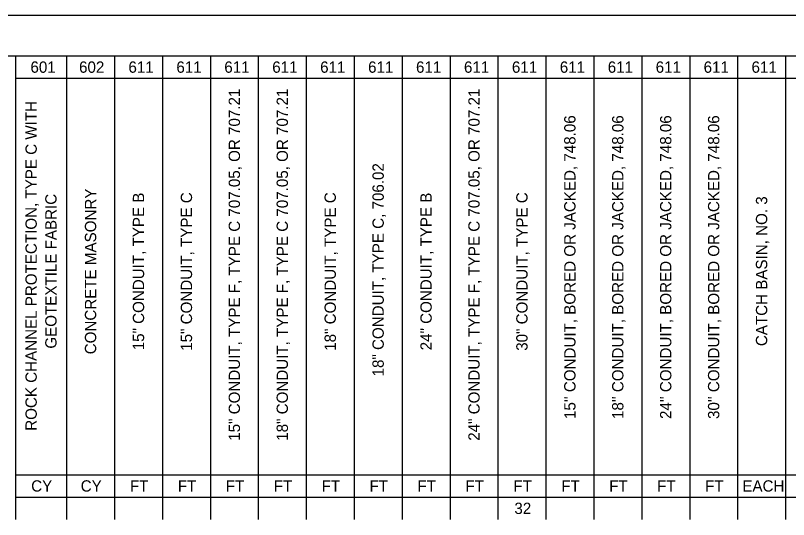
# Model space of a CAD drawing. Extents: x 0.2 to 34.2, y 0 to 22.
# Drawn here: x 14.91 to 24.47, y 15.79 to 22.03 of the extents above; entities that cross this region are included whole.
import ezdxf

# ---------------------------------------------------------------- set-up
doc = ezdxf.new("R2010")
doc.units = 0
for name, color, linetype in [('SH_Border', 7, 'Continuous'), ('SH_Cut_Line', 7, 'Continuous'), ('SH_Text', 7, 'Continuous')]:
    doc.layers.add(name, color=color, linetype=linetype)

msp = doc.modelspace()

# ---------------------------------------------------------------- linework, layer by layer
at = {"layer": 'SH_Border'}
msp.add_lwpolyline([(1.692, 21.5253), (33.692, 21.5253), (33.692, 0.5253), (1.692, 0.5253)], close=True, dxfattribs=at)
at = {"layer": 'SH_Cut_Line'}
msp.add_lwpolyline([(0.192, 0.0253), (34.192, 0.0253), (34.192, 22.0253), (0.192, 22.0253)], close=True, dxfattribs=at)
at = {"layer": 'SH_Text'}
for p, q in [((14.908, 21.5253), (15.5405, 21.5253)), ((14.908, 21.5253), (14.908, 21.2486)), ((15.5405, 21.5253), (24.4346, 21.5253)), ((15.5405, 21.5253), (15.5405, 21.2486)), ((16.1334, 21.5253), (16.1334, 21.2486)), ((16.7264, 21.5253), (16.7264, 21.2486)), ((17.3193, 21.5253), (17.3193, 21.2486)), ((17.9122, 21.5253), (17.9122, 21.2486)), ((18.5052, 21.5253), (18.5052, 21.2486)), ((19.0981, 21.5253), (19.0981, 21.2486)), ((19.6911, 21.5253), (19.6911, 21.2486)), ((20.284, 21.5253), (20.284, 21.2486)), ((20.8769, 21.5253), (20.8769, 21.2486)), ((21.4699, 21.5253), (21.4699, 21.2486)), ((22.0628, 21.5253), (22.0628, 21.2486)), ((22.6558, 21.5253), (22.6558, 21.2486)), ((23.2487, 21.5253), (23.2487, 21.2486)), ((23.8417, 21.5253), (23.8417, 21.2486)), ((24.4346, 21.5253), (32.1955, 21.5253)), ((24.4346, 21.5253), (24.4346, 21.2486)), ((14.908, 21.2486), (15.5405, 21.2486)), ((14.908, 21.2486), (14.908, 20.9719)), ((15.5405, 21.2486), (24.4346, 21.2486)), ((15.5405, 21.2486), (15.5405, 20.9719)), ((16.1334, 21.2486), (16.1334, 20.9719)), ((16.7264, 21.2486), (16.7264, 20.9719)), ((17.3193, 21.2486), (17.3193, 20.9719)), ((17.9122, 21.2486), (17.9122, 20.9719)), ((18.5052, 21.2486), (18.5052, 20.9719)), ((19.0981, 21.2486), (19.0981, 20.9719)), ((19.6911, 21.2486), (19.6911, 20.9719)), ((20.284, 21.2486), (20.284, 20.9719)), ((20.8769, 21.2486), (20.8769, 20.9719)), ((21.4699, 21.2486), (21.4699, 20.9719)), ((22.0628, 21.2486), (22.0628, 20.9719)), ((22.6558, 21.2486), (22.6558, 20.9719)), ((23.2487, 21.2486), (23.2487, 20.9719)), ((23.8417, 21.2486), (23.8417, 20.9719)), ((24.4346, 21.2486), (32.1955, 21.2486)), ((24.4346, 21.2486), (24.4346, 20.9719)), ((14.908, 20.9719), (14.908, 20.6952)), ((15.5405, 20.9719), (15.5405, 20.6952)), ((16.1334, 20.9719), (16.1334, 20.6952)), ((16.7264, 20.9719), (16.7264, 20.6952)), ((17.3193, 20.9719), (17.3193, 20.6952)), ((17.9122, 20.9719), (17.9122, 20.6952)), ((18.5052, 20.9719), (18.5052, 20.6952)), ((19.0981, 20.9719), (19.0981, 20.6952)), ((19.6911, 20.9719), (19.6911, 20.6952)), ((20.284, 20.9719), (20.284, 20.6952)), ((20.8769, 20.9719), (20.8769, 20.6952)), ((21.4699, 20.9719), (21.4699, 20.6952)), ((22.0628, 20.9719), (22.0628, 20.6952)), ((22.6558, 20.9719), (22.6558, 20.6952)), ((23.2487, 20.9719), (23.2487, 20.6952)), ((23.8417, 20.9719), (23.8417, 20.6952)), ((24.4346, 20.9719), (24.4346, 20.6952)), ((14.908, 20.6952), (14.908, 20.4184)), ((15.5405, 20.6952), (15.5405, 20.4184)), ((16.1334, 20.6952), (16.1334, 20.4184)), ((16.7264, 20.6952), (16.7264, 20.4184)), ((17.3193, 20.6952), (17.3193, 20.4184)), ((17.9122, 20.6952), (17.9122, 20.4184)), ((18.5052, 20.6952), (18.5052, 20.4184)), ((19.0981, 20.6952), (19.0981, 20.4184)), ((19.6911, 20.6952), (19.6911, 20.4184)), ((20.284, 20.6952), (20.284, 20.4184)), ((20.8769, 20.6952), (20.8769, 20.4184)), ((21.4699, 20.6952), (21.4699, 20.4184)), ((22.0628, 20.6952), (22.0628, 20.4184)), ((22.6558, 20.6952), (22.6558, 20.4184)), ((23.2487, 20.6952), (23.2487, 20.4184)), ((23.8417, 20.6952), (23.8417, 20.4184)), ((24.4346, 20.6952), (24.4346, 20.4184)), ((14.908, 20.4184), (14.908, 20.1417)), ((15.5405, 20.4184), (15.5405, 20.1417)), ((16.1334, 20.4184), (16.1334, 20.1417)), ((16.7264, 20.4184), (16.7264, 20.1417)), ((17.3193, 20.4184), (17.3193, 20.1417)), ((17.9122, 20.4184), (17.9122, 20.1417)), ((18.5052, 20.4184), (18.5052, 20.1417)), ((19.0981, 20.4184), (19.0981, 20.1417)), ((19.6911, 20.4184), (19.6911, 20.1417)), ((20.284, 20.4184), (20.284, 20.1417)), ((20.8769, 20.4184), (20.8769, 20.1417)), ((21.4699, 20.4184), (21.4699, 20.1417)), ((22.0628, 20.4184), (22.0628, 20.1417)), ((22.6558, 20.4184), (22.6558, 20.1417)), ((23.2487, 20.4184), (23.2487, 20.1417)), ((23.8417, 20.4184), (23.8417, 20.1417)), ((24.4346, 20.4184), (24.4346, 20.1417)), ((14.908, 20.1417), (14.908, 19.865)), ((15.5405, 20.1417), (15.5405, 19.865)), ((16.1334, 20.1417), (16.1334, 19.865)), ((16.7264, 20.1417), (16.7264, 19.865)), ((17.3193, 20.1417), (17.3193, 19.865)), ((17.9122, 20.1417), (17.9122, 19.865)), ((18.5052, 20.1417), (18.5052, 19.865)), ((19.0981, 20.1417), (19.0981, 19.865)), ((19.6911, 20.1417), (19.6911, 19.865)), ((20.284, 20.1417), (20.284, 19.865)), ((20.8769, 20.1417), (20.8769, 19.865)), ((21.4699, 20.1417), (21.4699, 19.865)), ((22.0628, 20.1417), (22.0628, 19.865)), ((22.6558, 20.1417), (22.6558, 19.865)), ((23.2487, 20.1417), (23.2487, 19.865)), ((23.8417, 20.1417), (23.8417, 19.865)), ((24.4346, 20.1417), (24.4346, 19.865)), ((14.908, 19.865), (14.908, 19.5883)), ((15.5405, 19.865), (15.5405, 19.5883)), ((16.1334, 19.865), (16.1334, 19.5883)), ((16.7264, 19.865), (16.7264, 19.5883)), ((17.3193, 19.865), (17.3193, 19.5883)), ((17.9122, 19.865), (17.9122, 19.5883)), ((18.5052, 19.865), (18.5052, 19.5883)), ((19.0981, 19.865), (19.0981, 19.5883)), ((19.6911, 19.865), (19.6911, 19.5883)), ((20.284, 19.865), (20.284, 19.5883)), ((20.8769, 19.865), (20.8769, 19.5883)), ((21.4699, 19.865), (21.4699, 19.5883)), ((22.0628, 19.865), (22.0628, 19.5883)), ((22.6558, 19.865), (22.6558, 19.5883)), ((23.2487, 19.865), (23.2487, 19.5883)), ((23.8417, 19.865), (23.8417, 19.5883)), ((24.4346, 19.865), (24.4346, 19.5883)), ((14.908, 19.5883), (14.908, 19.3116)), ((15.5405, 19.5883), (15.5405, 19.3116)), ((16.1334, 19.5883), (16.1334, 19.3116)), ((16.7264, 19.5883), (16.7264, 19.3116)), ((17.3193, 19.5883), (17.3193, 19.3116)), ((17.9122, 19.5883), (17.9122, 19.3116)), ((18.5052, 19.5883), (18.5052, 19.3116)), ((19.0981, 19.5883), (19.0981, 19.3116)), ((19.6911, 19.5883), (19.6911, 19.3116)), ((20.284, 19.5883), (20.284, 19.3116)), ((20.8769, 19.5883), (20.8769, 19.3116)), ((21.4699, 19.5883), (21.4699, 19.3116)), ((22.0628, 19.5883), (22.0628, 19.3116)), ((22.6558, 19.5883), (22.6558, 19.3116)), ((23.2487, 19.5883), (23.2487, 19.3116)), ((23.8417, 19.5883), (23.8417, 19.3116)), ((24.4346, 19.5883), (24.4346, 19.3116)), ((14.908, 19.3116), (14.908, 19.0349)), ((15.5405, 19.3116), (15.5405, 19.0349)), ((16.1334, 19.3116), (16.1334, 19.0349)), ((16.7264, 19.3116), (16.7264, 19.0349)), ((17.3193, 19.3116), (17.3193, 19.0349)), ((17.9122, 19.3116), (17.9122, 19.0349)), ((18.5052, 19.3116), (18.5052, 19.0349)), ((19.0981, 19.3116), (19.0981, 19.0349)), ((19.6911, 19.3116), (19.6911, 19.0349)), ((20.284, 19.3116), (20.284, 19.0349)), ((20.8769, 19.3116), (20.8769, 19.0349)), ((21.4699, 19.3116), (21.4699, 19.0349)), ((22.0628, 19.3116), (22.0628, 19.0349)), ((22.6558, 19.3116), (22.6558, 19.0349)), ((23.2487, 19.3116), (23.2487, 19.0349)), ((23.8417, 19.3116), (23.8417, 19.0349)), ((24.4346, 19.3116), (24.4346, 19.0349)), ((14.908, 19.0349), (14.908, 18.7582)), ((15.5405, 19.0349), (15.5405, 18.7582)), ((16.1334, 19.0349), (16.1334, 18.7582)), ((16.7264, 19.0349), (16.7264, 18.7582)), ((17.3193, 19.0349), (17.3193, 18.7582)), ((17.9122, 19.0349), (17.9122, 18.7582)), ((18.5052, 19.0349), (18.5052, 18.7582)), ((19.0981, 19.0349), (19.0981, 18.7582)), ((19.6911, 19.0349), (19.6911, 18.7582)), ((20.284, 19.0349), (20.284, 18.7582)), ((20.8769, 19.0349), (20.8769, 18.7582)), ((21.4699, 19.0349), (21.4699, 18.7582)), ((22.0628, 19.0349), (22.0628, 18.7582)), ((22.6558, 19.0349), (22.6558, 18.7582)), ((23.2487, 19.0349), (23.2487, 18.7582)), ((23.8417, 19.0349), (23.8417, 18.7582)), ((24.4346, 19.0349), (24.4346, 18.7582)), ((14.908, 18.7582), (14.908, 18.4815)), ((15.5405, 18.7582), (15.5405, 18.4815)), ((16.1334, 18.7582), (16.1334, 18.4815)), ((16.7264, 18.7582), (16.7264, 18.4815)), ((17.3193, 18.7582), (17.3193, 18.4815)), ((17.9122, 18.7582), (17.9122, 18.4815)), ((18.5052, 18.7582), (18.5052, 18.4815)), ((19.0981, 18.7582), (19.0981, 18.4815)), ((19.6911, 18.7582), (19.6911, 18.4815)), ((20.284, 18.7582), (20.284, 18.4815)), ((20.8769, 18.7582), (20.8769, 18.4815)), ((21.4699, 18.7582), (21.4699, 18.4815)), ((22.0628, 18.7582), (22.0628, 18.4815)), ((22.6558, 18.7582), (22.6558, 18.4815)), ((23.2487, 18.7582), (23.2487, 18.4815)), ((23.8417, 18.7582), (23.8417, 18.4815)), ((24.4346, 18.7582), (24.4346, 18.4815)), ((14.908, 18.4815), (14.908, 18.2048)), ((15.5405, 18.4815), (15.5405, 18.2048)), ((16.1334, 18.4815), (16.1334, 18.2048)), ((16.7264, 18.4815), (16.7264, 18.2048)), ((17.3193, 18.4815), (17.3193, 18.2048)), ((17.9122, 18.4815), (17.9122, 18.2048)), ((18.5052, 18.4815), (18.5052, 18.2048)), ((19.0981, 18.4815), (19.0981, 18.2048)), ((19.6911, 18.4815), (19.6911, 18.2048)), ((20.284, 18.4815), (20.284, 18.2048)), ((20.8769, 18.4815), (20.8769, 18.2048)), ((21.4699, 18.4815), (21.4699, 18.2048)), ((22.0628, 18.4815), (22.0628, 18.2048)), ((22.6558, 18.4815), (22.6558, 18.2048)), ((23.2487, 18.4815), (23.2487, 18.2048)), ((23.8417, 18.4815), (23.8417, 18.2048)), ((24.4346, 18.4815), (24.4346, 18.2048)), ((14.908, 18.2048), (14.908, 16.3469)), ((15.5405, 18.2048), (15.5405, 16.3469)), ((16.1334, 18.2048), (16.1334, 16.3469)), ((16.7264, 18.2048), (16.7264, 16.3469)), ((17.3193, 18.2048), (17.3193, 16.3469)), ((17.9122, 18.2048), (17.9122, 16.3469)), ((18.5052, 18.2048), (18.5052, 16.3469)), ((19.0981, 18.2048), (19.0981, 16.3469)), ((19.6911, 18.2048), (19.6911, 16.3469)), ((20.284, 18.2048), (20.284, 16.3469)), ((20.8769, 18.2048), (20.8769, 16.3469)), ((21.4699, 18.2048), (21.4699, 16.3469)), ((22.0628, 18.2048), (22.0628, 16.3469)), ((22.6558, 18.2048), (22.6558, 16.3469)), ((23.2487, 18.2048), (23.2487, 16.3469)), ((23.8417, 18.2048), (23.8417, 16.3469)), ((24.4346, 18.2048), (24.4346, 16.3469)), ((14.908, 16.3469), (15.5405, 16.3469)), ((14.908, 16.3469), (14.908, 16.0702)), ((15.5405, 16.3469), (24.4346, 16.3469)), ((15.5405, 16.3469), (15.5405, 16.0702)), ((16.1334, 16.3469), (16.1334, 16.0702)), ((16.7264, 16.3469), (16.7264, 16.0702)), ((17.3193, 16.3469), (17.3193, 16.0702)), ((17.9122, 16.3469), (17.9122, 16.0702)), ((18.5052, 16.3469), (18.5052, 16.0702)), ((19.0981, 16.3469), (19.0981, 16.0702)), ((19.6911, 16.3469), (19.6911, 16.0702)), ((20.284, 16.3469), (20.284, 16.0702)), ((20.8769, 16.3469), (20.8769, 16.0702)), ((21.4699, 16.3469), (21.4699, 16.0702)), ((22.0628, 16.3469), (22.0628, 16.0702)), ((22.6558, 16.3469), (22.6558, 16.0702)), ((23.2487, 16.3469), (23.2487, 16.0702)), ((23.8417, 16.3469), (23.8417, 16.0702)), ((24.4346, 16.3469), (32.1955, 16.3469)), ((24.4346, 16.3469), (24.4346, 16.0702)), ((14.908, 16.0702), (15.5405, 16.0702)), ((14.908, 16.0702), (14.908, 15.7935)), ((15.5405, 16.0702), (24.4346, 16.0702)), ((15.5405, 16.0702), (15.5405, 15.7935)), ((16.1334, 16.0702), (16.1334, 15.7935)), ((16.7264, 16.0702), (16.7264, 15.7935)), ((17.3193, 16.0702), (17.3193, 15.7935)), ((17.9122, 16.0702), (17.9122, 15.7935)), ((18.5052, 16.0702), (18.5052, 15.7935)), ((19.0981, 16.0702), (19.0981, 15.7935)), ((19.6911, 16.0702), (19.6911, 15.7935)), ((20.284, 16.0702), (20.284, 15.7935)), ((20.8769, 16.0702), (20.8769, 15.7935)), ((21.4699, 16.0702), (21.4699, 15.7935)), ((22.0628, 16.0702), (22.0628, 15.7935)), ((22.6558, 16.0702), (22.6558, 15.7935)), ((23.2487, 16.0702), (23.2487, 15.7935)), ((23.8417, 16.0702), (23.8417, 15.7935)), ((24.4346, 16.0702), (32.1955, 16.0702)), ((24.4346, 16.0702), (24.4346, 15.7935))]:
    msp.add_line(p, q, dxfattribs=at)

# ---------------------------------------------------------------- texts
for s, p in [('601', (15.0936, 21.3169)), ('602', (15.6948, 21.3169)), ('611', (16.3058, 21.3169)), ('611', (16.8987, 21.3169)), ('611', (17.4917, 21.3169)), ('611', (18.0846, 21.3169)), ('611', (18.6776, 21.3169)), ('611', (19.2705, 21.3169)), ('611', (19.8635, 21.3169)), ('611', (20.4564, 21.3169)), ('611', (21.0493, 21.3169)), ('611', (21.6423, 21.3169)), ('611', (22.2352, 21.3169)), ('611', (22.8282, 21.3169)), ('611', (23.4211, 21.3169)), ('611', (24.014, 21.3169)), ('CY', (15.1026, 16.1386)), ('CY', (15.7153, 16.1386)), ('FT', (16.3241, 16.1386)), ('FT', (16.917, 16.1386)), ('FT', (17.51, 16.1386)), ('FT', (18.1029, 16.1386)), ('FT', (18.6959, 16.1386)), ('FT', (19.2888, 16.1386)), ('FT', (19.8818, 16.1386)), ('FT', (20.4747, 16.1386)), ('FT', (21.0676, 16.1386)), ('FT', (21.6606, 16.1386)), ('FT', (22.2535, 16.1386)), ('FT', (22.8465, 16.1386)), ('FT', (23.4394, 16.1386)), ('EACH', (23.9006, 16.1386)), ('32', (21.0802, 15.8619))]:
    msp.add_text(s, height=0.14, dxfattribs=at).set_placement(p)
for s, p in [('15" CONDUIT, TYPE F, TYPE C 707.05, OR 707.21', (17.6858, 16.7674)), ('18" CONDUIT, TYPE F, TYPE C 707.05, OR 707.21', (18.2787, 16.7674)), ('24" CONDUIT, TYPE F, TYPE C 707.05, OR 707.21', (20.6505, 16.7674)), ('ROCK CHANNEL PROTECTION, TYPE C WITH ', (15.1717, 16.8909)), ("15'' CONDUIT, BORED OR JACKED, 748.06", (21.8364, 17.0366)), ("18'' CONDUIT, BORED OR JACKED, 748.06", (22.4293, 17.0366)), ("24'' CONDUIT, BORED OR JACKED, 748.06", (23.0222, 17.0366)), ("30'' CONDUIT, BORED OR JACKED, 748.06", (23.6152, 17.0366)), ('18" CONDUIT, TYPE C, 706.02', (19.4646, 17.563)), ('GEOTEXTILE FABRIC', (15.4167, 17.906)), ('CONCRETE MASONRY', (15.9069, 17.8364)), ('15" CONDUIT, TYPE B', (16.4999, 17.8859)), ('15" CONDUIT, TYPE C', (17.0928, 17.8798)), ('18" CONDUIT, TYPE C', (18.8717, 17.8798)), ('24" CONDUIT, TYPE B', (20.0575, 17.8859)), ('30" CONDUIT, TYPE C', (21.2434, 17.8798)), ('CATCH BASIN, NO. 3', (24.2081, 17.9376))]:
    msp.add_text(s, height=0.14, rotation=90, dxfattribs=at).set_placement(p)

doc.saveas('drawing.dxf')
